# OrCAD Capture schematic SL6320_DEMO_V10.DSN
size Custom; title: SL6320_DEMO_V1.0; rev: V01; note: 4
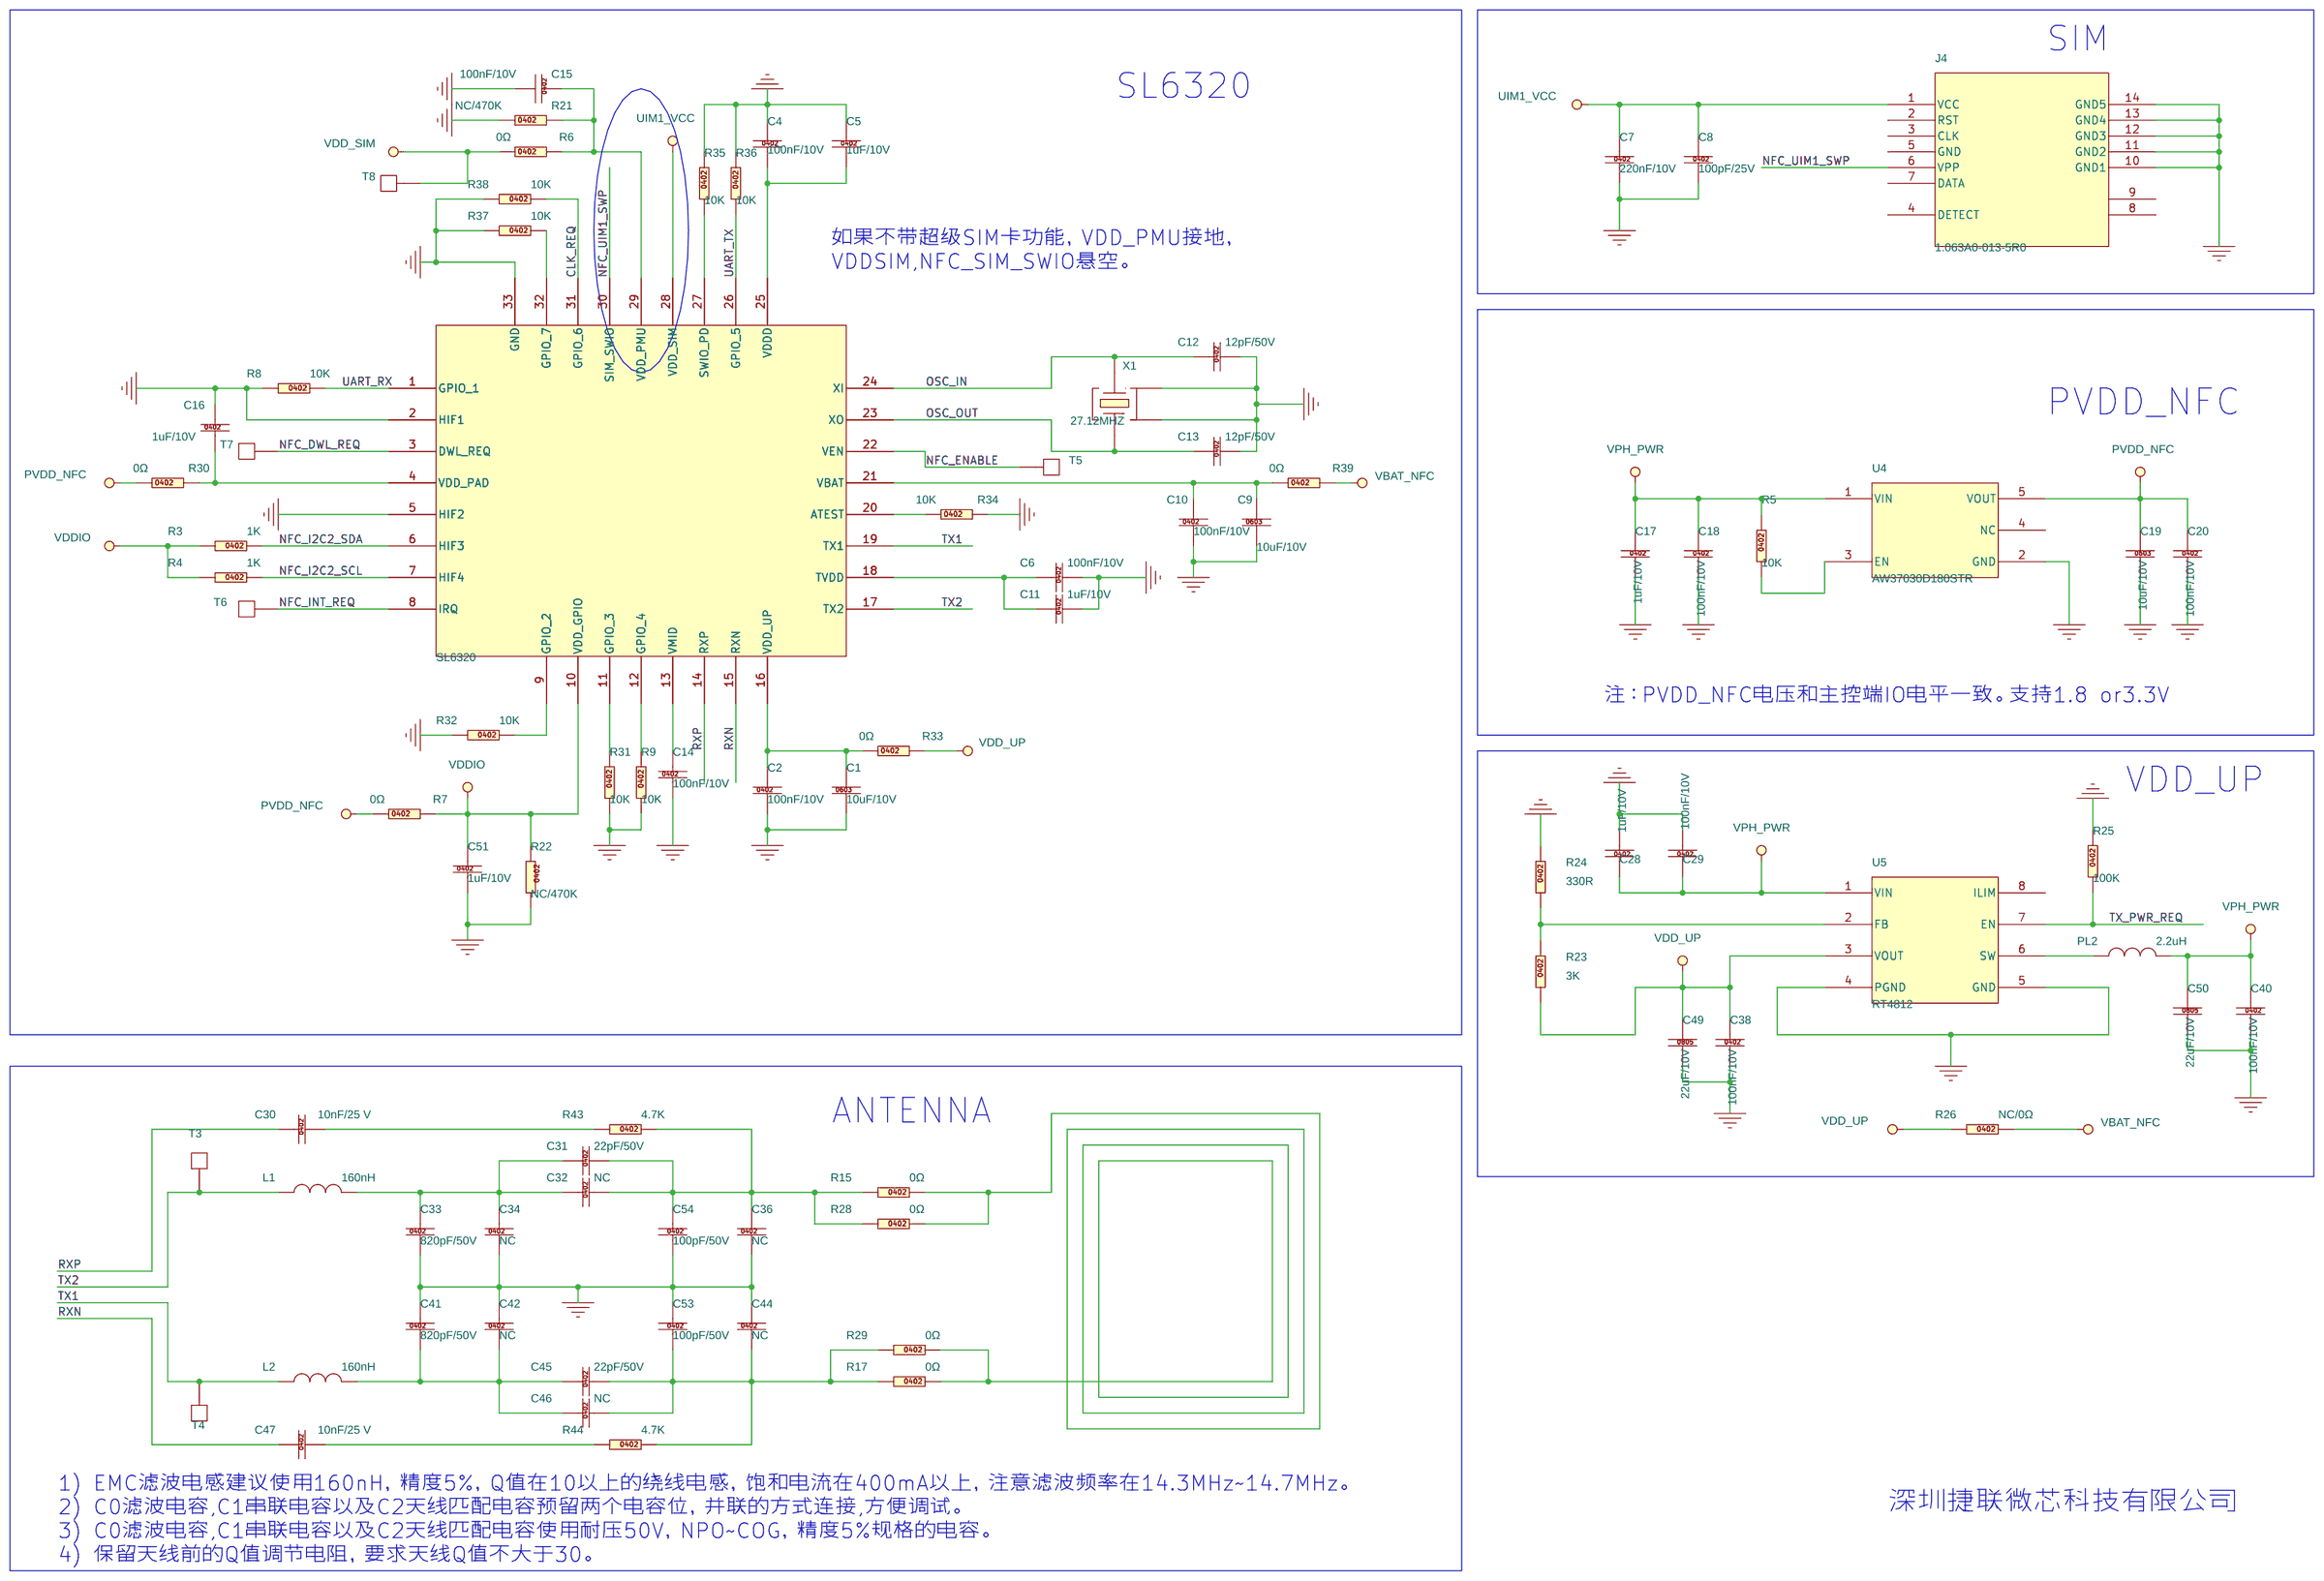
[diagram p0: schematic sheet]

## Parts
C1  10uF/10V  [C0603-10]
C2  100nF/10V  [C0402-04]
C4  100nF/10V  [C0402-04]
C5  1uF/10V  [C0402-06]
C6  100nF/10V  [C0402-04]
C7  220nF/10V  [C0402-05]
C8  100pF/25V  [C0402-06]
C9  10uF/10V  [C0603-10]
C10  100nF/10V  [C0402-04]
C11  1uF/10V  [C0402-06]
C12  12pF/50V  [C0402-06]
C13  12pF/50V  [C0402-06]
C14  100nF/10V  [C0402-04]
C15  100nF/10V  [C0402-04]
C16  1uF/10V  [C0402-06]
C17  1uF/10V  [C0402-06]
C18  100nF/10V  [C0402-04]
C19  10uF/10V  [C0603-10]
C20  100nF/10V  [C0402-04]
C28  1uF/10V  [C0402-06]
C29  100nF/10V  [C0402-04]
C30  10nF/25 V  [C0402-05]
C31  22pF/50V  [C0402-06]
C32  NC  [C0402-06]
C33  820pF/50V  [C0402-06]
C34  NC  [C0402-06]
C36  NC  [C0402-06]
C38  100nF/10V  [C0402-04]
C40  100nF/10V  [C0402-04]
C41  820pF/50V  [C0402-06]
C42  NC  [C0402-06]
C44  NC  [C0402-06]
C45  22pF/50V  [C0402-06]
C46  NC  [C0402-06]
C47  10nF/25 V  [C0402-05]
C49  22uF/10V  [C0805-09]
C50  22uF/10V  [C0805-09]
C51  1uF/10V  [C0402-06]
C53  100pF/50V  [C0402-06]
C54  100pF/50V  [C0402-06]
J4  1.063A0-013-5R0  [MC02-61150-7R_SIM1]
L1  160nH  [C0603-10]
L2  160nH  [C0603-10]
PL2  2.2uH  [PL4040-18]
R3  1K  [R0402-04]
R4  1K  [R0402-04]
R5  10K  [R0402-04]
R6  0Ω  [R0402-04]
R7  0Ω  [R0402-04]
R8  10K  [R0402-04]
R9  10K  [R0402-04]
R15  0Ω  [R0402-04]
R17  0Ω  [R0402-04]
R21  NC/470K  [R0402-04]
R22  NC/470K  [R0402-04]
R23  3K  [R0402-04]
R24  330R  [R0402-04]
R25  100K  [R0402-04]
R26  NC/0Ω  [R0402-04]
R28  0Ω  [R0402-04]
R29  0Ω  [R0402-04]
R30  0Ω  [R0402-04]
R31  10K  [R0402-04]
R32  10K  [R0402-04]
R33  0Ω  [R0402-04]
R34  10K  [R0402-04]
R35  10K  [R0402-04]
R36  10K  [R0402-04]
R37  10K  [R0402-04]
R38  10K  [R0402-04]
R39  0Ω  [R0402-04]
R43  4.7K  [R0402-04]
R44  4.7K  [R0402-04]
T3  0.24mm  [TP1_0]
T4  0.24mm  [TP1_0]
T5  0.24mm  [TP1_0]
T6  0.24mm  [TP1_0]
T7  0.24mm  [TP1_0]
T8  0.24mm  [TP1_0]
U4  AW37030D180STR  [SOT23-5-12]
U5  RT4812  [TSOT-23-8]
U8  SL6320  [QFNWB5X5-32L-Q]
X1  27.12MHZ  [X4-3225-09]

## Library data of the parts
C1 C9 C19 = 31002000154: PART_NAME: 陶瓷电容
C2 C4 C6 C10 C14 C15 C18 C20 C29 C38 C40 = 31002000872: PART_NAME: 陶瓷电容
C5 C11 C16 C17 C28 C51 = 31002000574: PART_NAME: 陶瓷电容
C7 = 31002000797
C8 = 31002000490
C12 C13 = 31002000217
C30 C47 = C0402: 陶瓷电容/10nF/±10%/25V/X7R/0402/0.55mm/-55~125℃; Manufacturer: MURATA; Part Name: 陶瓷电容; Part Number: GRM155R71E103KA01D; Part_Number: 31002000285
C31-C34 C36 C42 C44-C46 = 31002000729: PART_NAME: 陶瓷电容
C41 = 31002000729: 陶瓷??2022pF/±5%/25V/C0G/0402/0.55mm/-55 to 125℃℃; PART_NAME: 陶瓷电容
C49 C50 = 31002000766
C53 C54 = 31002000249
J4 = 1_2.063A0-013-5R0
L1 = MWSD1608F
L2 = MWSD1608F_1
PL2 = 31008000121: PART_NAME: 功率电感
R3 R4 = 31003001157: PART_NAME: 贴片电阻
R5 R8 R9 R31 R32 R34-R38 = 31003000947: PART_NAME: 贴片电阻
R6 R7 R15 R17 R26 R28-R30 R33 R39 = 31003001357: PART_NAME: 贴片电阻
R21 R22 = 31003001082
R23 = 31003000334
R24 = 31003000950
R25 = 31003000948
R43 R44 = 31003000354
T3-T8 = TP_0.24mm
U4 = AW37030D180STR
U5 = RT4812_0
U8 = SL6320_0
X1 = XTAL_4P: 无源晶振/8 MHz/20 ppm/30 ppm/12 pF/500 Ω/3 pF/0.0002 W/3.2 mm*2.5 mm*0.75 mm/-40~85℃℃; Manufacturer: 鸿星/HOSONIC; Part Name: 无源晶振; Part Number: E3SB8E0009202E; Part_Number: 31053000072

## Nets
GND: C1.2 C2.2 C4.1 C5.1 C6.2 C7.2 C8.2 C9.2 C10.2 C11.2 C12.2 C13.2 C14.2 C15.2 C16.1 C17.2 C18.2 C19.2 C20.2 C28.2 C29.2 C33.2 C34.2 C36.2 C38.2 C40.2 C41.1 C42.1 C44.1 C49.2 C50.2 C51.2 C53.1 C54.2 J4.10(GND1) J4.11(GND2) J4.12(GND3) J4.13(GND4) J4.14(GND5) R8.1 R9.1 R21.2 R22.1 R24.2 R25.2 R31.1 R32.1 R34.1 R35.2 R36.2 R37.1 R38.1 U4.2(GND) U5.4(PGND) U5.5(GND) U8.2(HIF1) U8.5(HIF2) U8.33(GND) X1.2 X1.4
PVDD_NFC: C19.1 C20.1 R7.2 R30.2 U4.5(VOUT)
VBAT_NFC: R26.2 R39.1
VDD_SIM: R6.2 T8.1
VDD_UP: C38.1 C49.1 R23.1 R26.1 R33.1 U5.3(VOUT)
VDDIO: C51.1 R3.1 R4.1 R7.1 R22.2 U8.10(VDD_GPIO)
CLK_REQ: R38.2 U8.31(GPIO_6)
NFC_DWL_REQ: T7.1 U8.3(DWL_REQ)
NFC_ENABLE: T5.1 U8.22(VEN)
NFC_I2C2_SCL: R4.2 U8.7(HIF4)
NFC_I2C2_SDA: R3.2 U8.6(HIF3)
NFC_INT_REQ: T6.1 U8.8(IRQ)
NFC_UIM1_SWP: J4.6(VPP) U8.30(SIM_SWIO)
OSC_IN: C12.1 U8.24(XI) X1.1
OSC_OUT: C13.1 U8.23(XO) X1.3
RXN: C47.1 U8.15(RXN)
RXP: C30.1 U8.14(RXP)
TX1: L2.1 T4.1 U8.19(TX1)
TX2: L1.1 T3.1 U8.17(TX2)
TX_PWR_REQ: R25.1 U5.7(EN)
UART_RX: R8.2 U8.1(GPIO)
UART_TX: R36.1 U8.26(GPIO_5)
UIM1_VCC: C7.1 C8.1 J4.1(VCC) U8.28(VDD_SIM)
VPH_PWR: C17.1 C18.1 C28.1 C29.1 C40.1 C50.1 PL2.2 R5.2 U4.1(VIN) U5.1(VIN)
N04213: C14.1 U8.13(VMID)
N04221: C16.2 R30.1 U8.4(VDD_PAD)
N04549: R31.2 U8.11(GPIO_3)
N04553: R9.2 U8.12(GPIO_4)
N45533: R5.1 U4.3(EN)
N45753: R23.2 R24.1 U5.2(FB)
N45835: PL2.1 U5.6(SW)
N47264: R15.2 R17.2 R28.2 R29.2
N47284: C30.2 R43.1
N47288: C31.2 C32.2 C36.1 C54.1 R15.1 R28.1 R43.2
N47346: C31.1 C32.1 C33.1 C34.1 L1.2
N47750: C41.2 C42.2 C45.1 C46.1 L2.2
N47758: C44.2 C45.2 C46.2 C53.2 R17.1 R29.1 R44.2
N47968: C47.2 R44.1
N58200: R32.2 U8.9(GPIO_2)
N61294: C1.1 C2.1 R33.2 U8.16(VDD_UP)
N63767: C6.1 C11.1 U8.18(TVDD)
N64821: R34.2 U8.20(ATEST)
N65249: C9.1 C10.1 R39.2 U8.21(VBAT)
N67717: C4.2 C5.2 U8.25(VDDD)
N67981: R35.1 U8.27(SWIO_PD)
N69913: C15.1 R6.1 R21.1 U8.29(VDD_PMU)
N71544: R37.2 U8.32(GPIO_7)

Not connected (* = marked no-connect by the designer): J4 2(RST) 3(CLK) 4(DETECT) 5(GND) 7(DATA) 8 9; U4 4(NC); U5 8(ILIM)

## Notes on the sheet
- SIM
- SL6320
- 如果不带超级SIM卡功能，VDD_PMU接地，
  VDDSIM,NFC_SIM_SWIO悬空。
- PVDD_NFC
- 注：PVDD_NFC电压和主控端IO电平一致。支持1.8 or3.3V
- VDD_UP
- ANTENNA
- 1) EMC滤波电感建议使用160nH，精度5%，Q值在10以上的绕线电感，饱和电流在400mA以上，注意滤波频率在14.3MHz~14.7MHz。
  2) C0滤波电容,C1串联电容以及C2天线匹配电容预留两个电容位，并联的方式连接,方便调试。
  3) C0滤波电容,C1串联电容以及C2天线匹配电容使用耐压50V，NPO~COG，精度5%规格的电容。
  4) 保留天线前的Q值调节电阻，要求天线Q值不大于30。
- 深圳捷联微芯科技有限公司
